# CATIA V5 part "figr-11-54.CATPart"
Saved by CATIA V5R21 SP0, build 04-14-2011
Part number: Part1
Bounding box of the stored display mesh (mm): x -49.998 to 49.998, y -70 to 70, z 0 to 80.773
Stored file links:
  D:\CATIA V5R21 E-RESOURCES\CATIA-V5R21\catia-v5r21-prt\c11-catia-v5r21-prt\c11-catia-v5r21-figr-11-54.CATPart
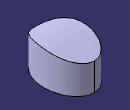
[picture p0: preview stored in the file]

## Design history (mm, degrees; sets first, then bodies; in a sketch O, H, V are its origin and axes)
Set1
  Extrude1: Element1 Sketch2, Lim1 82, Lim2 70, Direction yz-plane
Body1 (main body)
  Sketch1 on xy-plane, origin (0, 0, 0), H (1, 0, 0), V (0, 1, 0)
    ellipse A1 centre (0, 0) semi-axes 70, 50 rotation 90
    point P1 (50, 0)
    coincidence: P1 H, A1 P1
  Pad1: profile Sketch1, direction (0, 0, 1), length 84
  Split1: SplitPlane Extrude1
  Sketch2 on yz-plane, origin (0, 0, 0), H (0, 1, 0), V (0, 0, 1)
    spline S1 through (-90, 50) (-30, 80) (50, 70) (90, 60)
